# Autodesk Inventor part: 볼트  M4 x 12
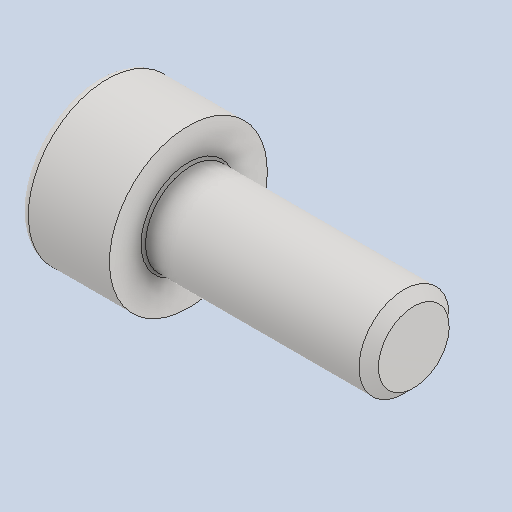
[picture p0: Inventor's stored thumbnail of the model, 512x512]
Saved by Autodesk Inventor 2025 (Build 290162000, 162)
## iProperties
Created: 2024-08
Part Number: 볼트  M4 x 12
Material: 스테인리스강
Description: 6각머리 태핑 나사
Document SubType Name: Modeling
Designer: hsj03
Density: 8.08 g/cm^3
Appearance: 기본값
Author: jhkim
Sending System: Autodesk Inventor 2025
Preprocessor: ST-DEVELOPER v20
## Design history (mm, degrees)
feature "Solid1"
node "솔리드1"
